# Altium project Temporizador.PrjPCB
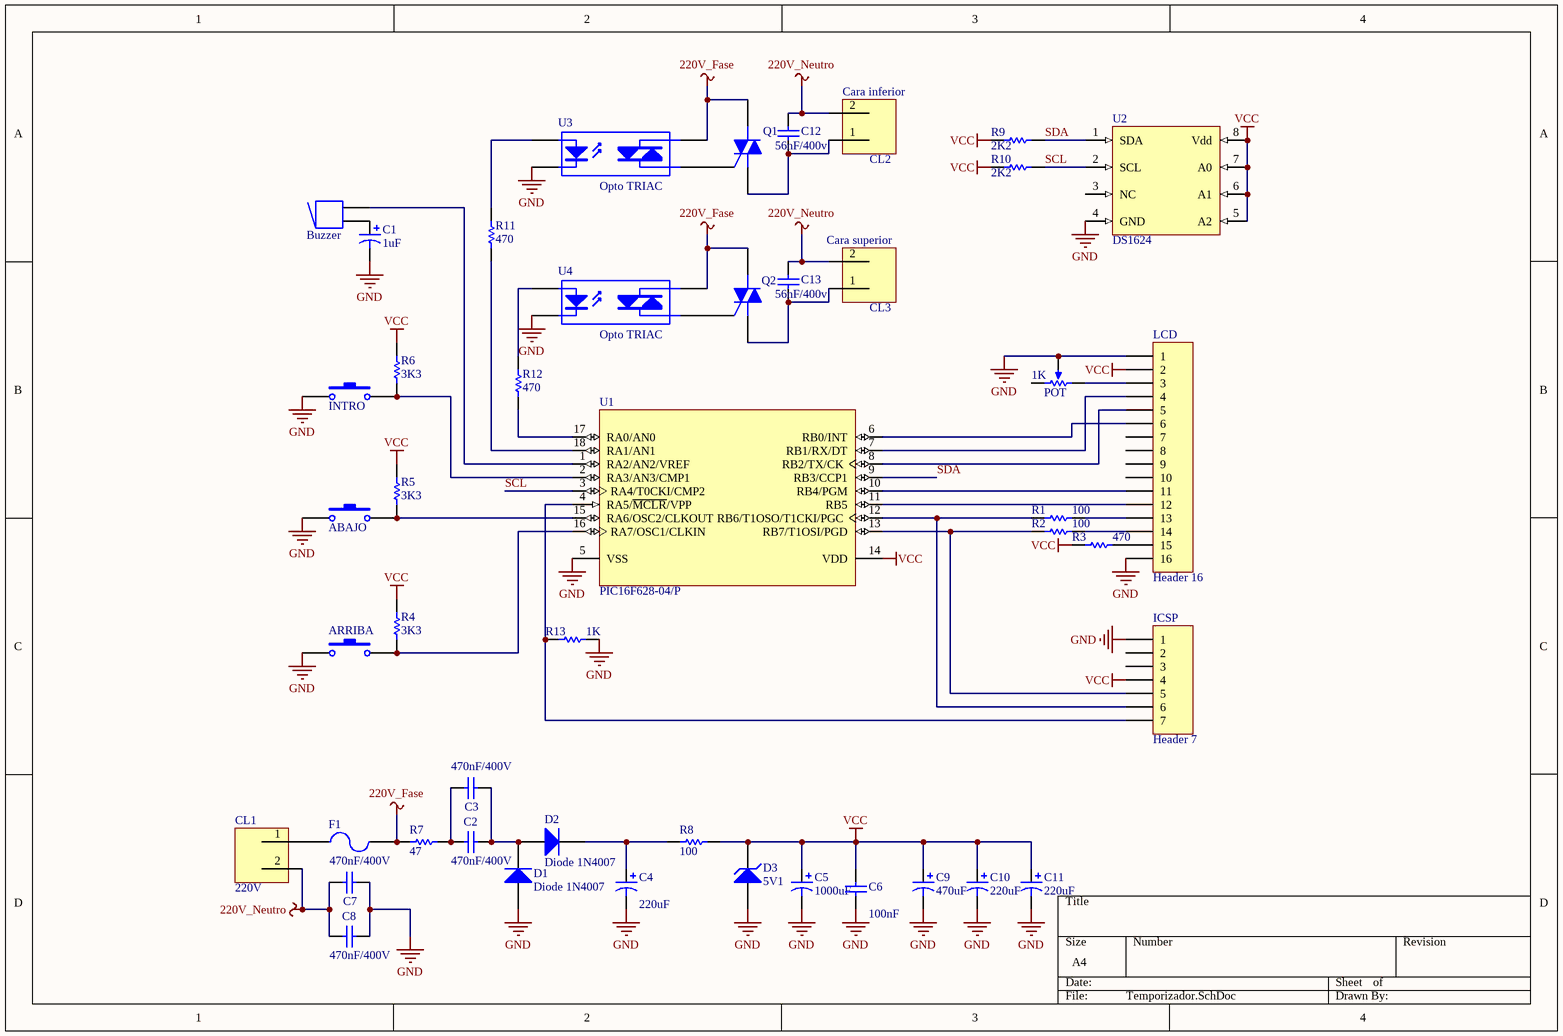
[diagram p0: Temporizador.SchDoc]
1 sheet, 46 parts. Net scope: global (net labels, ports and power ports of the same name join across sheets).
Board file: Temporizador.PcbDoc

## Sheet Temporizador.SchDoc
size A4

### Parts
ABAJO  SW-PB  [pulsador]  (value not drawn)
ARRIBA  SW-PB  [pulsador]  (value not drawn)
Buzzer  Buzzer  [BUZZER]  (value not drawn)
C1  value 1uF  [B]  (hidden comment: Cap Pol1)
C2  value 470nF/400V  [RAD-5]  (hidden comment: Cap)
C3  value 470nF/400V  [RAD-5]  (hidden comment: Cap)
C4  value 220uF  [CAPPR5-5x5]  (hidden comment: Cap Pol1)
C5  value 1000uF  [CAPPR5-5x5]  (hidden comment: Cap Pol1)
C6  value 100nF  [VP45-3.2]  (hidden comment: Cap)
C7  value 470nF/400V  [RAD-5]  (hidden comment: Cap)
C8  value 470nF/400V  [RAD-5]  (hidden comment: Cap)
C9  value 470uF  [CAPPR5-5x5]  (hidden comment: Cap Pol1)
C10  value 220uF  [CAPPR5-5x5]  (hidden comment: Cap Pol1)
C11  value 220uF  [CAPPR5-5x5]  (hidden comment: Cap Pol1)
C12  value 56nF/400v  [COND56K]  (hidden comment: Cap)
C13  value 56nF/400v  [COND56K]  (hidden comment: Cap)
CL1  220V  [Clema-2]
CL2  Cara inferior  [Clema-2]
CL3  Cara superior  [Clema-2]
D1  Diode 1N4007  [DO-41]
D2  Diode 1N4007  [DO-41]
D3  5V1  [do-41]
F1  Fuse 2  [FUSE]  (value not drawn)
ICSP  Header 7  [HDR1X7]
INTRO  SW-PB  [pulsador]  (value not drawn)
LCD  Header 16  [HDR1X16]
POT  value 1K  [potenciometro]  (hidden comment: RPot)
Q1  Triac  [369-03]  (value not drawn)
Q2  Triac  [369-03]  (value not drawn)
R1  value 100  [AXIAL-0.3]  (hidden comment: Res1)
R2  value 100  [AXIAL-0.3]  (hidden comment: Res1)
R3  value 470  [AXIAL-0.3]  (hidden comment: Res1)
R4  value 3K3  [AXIAL-0.3]  (hidden comment: Res1)
R5  value 3K3  [AXIAL-0.3]  (hidden comment: Res1)
R6  value 3K3  [AXIAL-0.3]  (hidden comment: Res1)
R7  value 47  [RES1W]  (hidden comment: Res1)
R8  value 100  [AXIAL-0.3]  (hidden comment: Res1)
R9  value 2K2  [AXIAL-0.3]  (hidden comment: Res1)
R10  value 2K2  [AXIAL-0.3]  (hidden comment: Res1)
R11  value 470  [AXIAL-0.3]  (hidden comment: Res1)
R12  value 470  [AXIAL-0.3]  (hidden comment: Res1)
R13  value 1K  [AXIAL-0.3]  (hidden comment: Res1)
U1  PIC16F628-04/P  [PDIP300-18]
U2  DS1624  [DIP-8]
U3  Opto TRIAC  [DIP-6]
U4  Opto TRIAC  [DIP-6]

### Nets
220V_Fase: F1.2 Q1.2(M2) Q2.2(M2) R7.2 U3.6(A/K) U4.6(A/K)
220V_Neutro: C7.1 C8.1 C12.2 C13.2 CL1.2 CL2.2 CL3.2
GND: ABAJO.1 ARRIBA.1 C1.2 C4.2 C5.2 C6.1 C7.2 C8.2 C9.2 C10.2 C11.2 D1.1(A) D3.1(A) ICSP.1 INTRO.1 LCD.1 LCD.16 POT.3(TAP) R13.2 U1.5(VSS) U2.4(GND) U3.2(K) U4.2(K)
VCC: C5.1 C6.2 C9.1 C10.1 C11.1 D3.2(K) ICSP.4 LCD.2 R3.1 R4.2 R5.2 R6.2 R8.1 R9.1 R10.1 U1.14(VDD) U2.5(A2) U2.6(A1) U2.7(A0) U2.8(Vdd)
SCL: R10.2 U1.3(RA4/T0CKI/CMP2) U2.2(SCL)
SDA: R9.2 U1.9(RB3/CCP1) U2.1(SDA)
NetABAJO_2: ABAJO.2 R5.1 U1.15(RA6/OSC2/CLKOUT)
NetARRIBA_2: ARRIBA.2 R4.1 U1.16(RA7/OSC1/CLKIN)
NetBuzzer_1: Buzzer.1 C1.1
NetBuzzer_2: Buzzer.2 U1.1(RA2/AN2/VREF)
NetC2_1: C2.1 C3.1 R7.1
NetC2_2: C2.2 C3.2 D1.2(K) D2.1(A)
NetC4_1: C4.1 D2.2(K) R8.2
NetC12_1: C12.1 CL2.1 Q1.1(M1)
NetC13_1: C13.1 CL3.1 Q2.1(M1)
NetCL1_1: CL1.1 F1.1
NetICSP_5: ICSP.5 R2.1 U1.13(RB7/T1OSI/PGD)
NetICSP_6: ICSP.6 R1.1 U1.12(RB6/T1OSO/T1CKI/PGC)
NetICSP_7: ICSP.7 R13.1 U1.4(RA5/~{MCLR}/VPP)
NetINTRO_2: INTRO.2 R6.1 U1.2(RA3/AN3/CMP1)
NetLCD_3: LCD.3 POT.1(TOP)
NetLCD_4: LCD.4 U1.7(RB1/RX/DT)
NetLCD_5: LCD.5 U1.8(RB2/TX/CK)
NetLCD_6: LCD.6 U1.6(RB0/INT)
NetLCD_11: LCD.11 U1.10(RB4/PGM)
NetLCD_12: LCD.12 U1.11(RB5)
NetLCD_13: LCD.13 R1.2
NetLCD_14: LCD.14 R2.2
NetLCD_15: LCD.15 R3.2
NetQ1_3: Q1.3(G) U3.4(A/K)
NetQ2_3: Q2.3(G) U4.4(A/K)
NetR11_1: R11.1 U1.18(RA1/AN1)
NetR11_2: R11.2 U3.1(A)
NetR12_1: R12.1 U1.17(RA0/AN0)
NetR12_2: R12.2 U4.1(A)

Not connected (* = marked no-connect by the designer): ICSP 2 3; LCD 7 8 9 10; POT 2(BOT); U2 3(NC)

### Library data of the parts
ABAJO ARRIBA INTRO = SW-PB: Switch
Buzzer = Buzzer: Magnetic Transducer Buzzer; Revision 1: Jul-2002: Re-released for DXP Platform.; Revision 2: 17-Dec-2003: Schematic revised, PCB Footprint replaced.
C1 C4 C5 C9-C11 = Cap Pol1: Polarized Capacitor (Radial)
C2 C3 C6-C8 C12 C13 = Cap: Capacitor
CL1-CL3 = Clema-2
D1 D2 = Diode 1N4007: 1 Amp General Purpose Rectifier
D3 = D Zener: Zener Diode
F1 = Fuse 2: Fuse
ICSP = Header 7: Header, 7-Pin
LCD = Header 16: Header, 16-Pin
POT = RPot: Potentiometer; Sim Note: Enter the Resistance value and the set point into parameter fields.; Set Position: 0.5
Q1 Q2 = Triac: Silicon Bidirectional Triode Thyristor; Note: Pin 2 is electrically connected to Pin 4 (TAB)
R1-R13 = Res1: Resistor
U1 = PIC16F628-04/P: FLASH-Based 8-Bit CMOS Microcontroller, 2K (x14-Bit words) FLASH, 224 Bytes RAM, 4 MHz, 18-Pin PDIP, 3.0 to 5.5V Supply Range, Commercial Temperature
U3 U4 = Opto TRIAC: Opto-Triac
